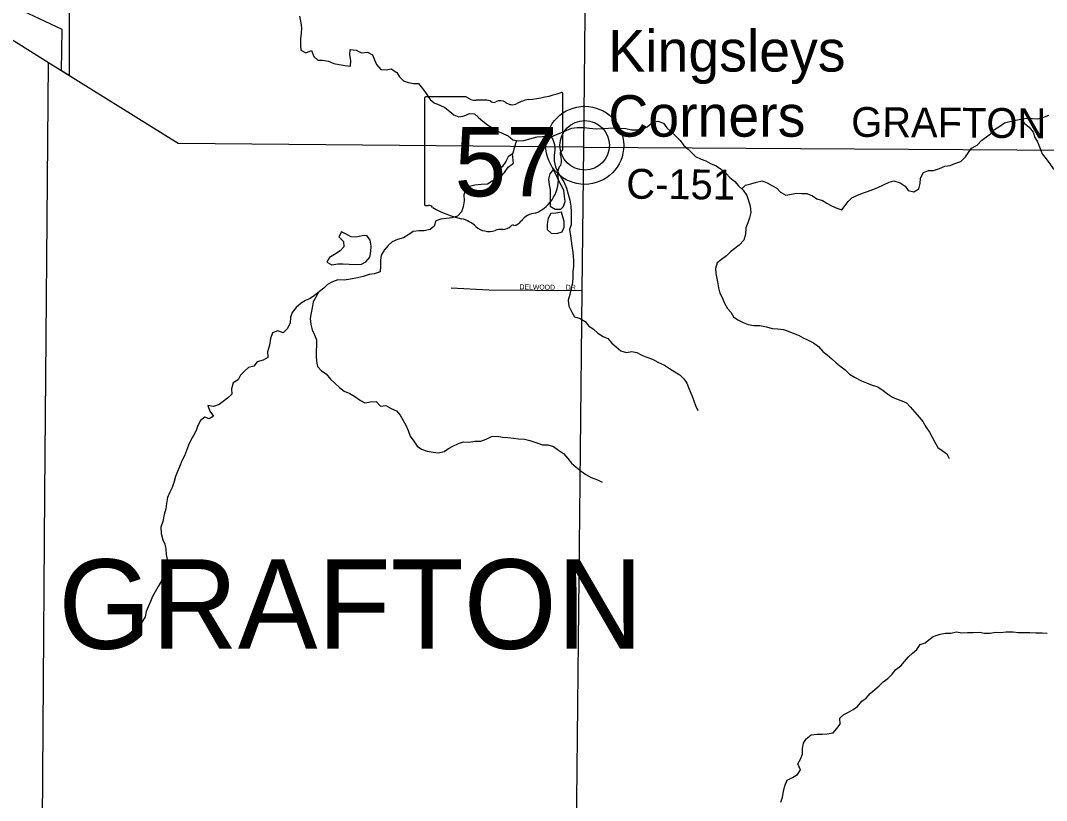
# Model space of a CAD drawing. Extents: x 1857828 to 2277390, y 930619 to 1324581.
# Drawn here: x 2094171 to 2104491, y 1181451 to 1189298 of the extents above; entities that cross this region are included whole.
import ezdxf

# ---------------------------------------------------------------- set-up
doc = ezdxf.new("R2010")
doc.units = 0
for name, color, linetype in [('GM_X_Corporation', 7, 'Continuous'), ('GM_X_County_Road', 7, 'Continuous'), ('GM_X_County_Road_Text', 7, 'Continuous'), ('GM_X_Minor_Lake', 7, 'Continuous'), ('GM_X_Minor_River', 7, 'Continuous'), ('GM_X_State_Location', 7, 'Continuous'), ('GM_X_State_Route', 7, 'Continuous'), ('GM_X_State_Shield', 7, 'Continuous'), ('GM_X_Township_Subdivision', 7, 'Continuous'), ('GM_X_Township_Subdivision_Text', 7, 'Continuous'), ('GM_X_Township_Text', 7, 'Continuous'), ('GM_X_Unincorporated', 7, 'Continuous'), ('GM_X_Unincorporated_Location', 7, 'Continuous'), ('GM_X_Unincorporated_Text', 7, 'Continuous')]:
    doc.layers.add(name, color=color, linetype=linetype)

msp = doc.modelspace()

# ---------------------------------------------------------------- linework, layer by layer
at = {"layer": 'GM_X_Corporation'}
msp.add_lwpolyline([(2093514, 1192144), (2096865, 1192069), (2096840, 1190794), (2094661, 1190795), (2094659, 1188744), (2094584, 1188791), (2094589, 1189208), (2094190, 1189394), (2094190, 1189397), (2093552, 1189568)], dxfattribs=at)
at = {"layer": 'GM_X_County_Road'}
for points in [[(2094381, 1179825), (2094381, 1179825), (2094416, 1184532), (2094454, 1188872)], [(2099838, 1188022), (2105283, 1187989)]]:
    msp.add_lwpolyline(points, dxfattribs=at)
at = {"layer": 'GM_X_Minor_Lake'}
for points in [[(2099119, 1187955), (2099077, 1187927), (2099051, 1187878), (2099017, 1187826), (2098967, 1187784), (2098953, 1187733), (2099006, 1187732)], [(2099006, 1187732), (2099039, 1187770), (2099077, 1187824), (2099129, 1187863), (2099119, 1187955)], [(2099529, 1187799), (2099495, 1187756), (2099483, 1187702), (2099487, 1187646), (2099497, 1187594), (2099500, 1187539), (2099500, 1187485), (2099498, 1187429), (2099548, 1187401), (2099605, 1187399), (2099631, 1187428)], [(2099529, 1187799), (2099495, 1187756), (2099483, 1187702), (2099487, 1187646), (2099497, 1187594), (2099500, 1187539), (2099500, 1187485), (2099498, 1187429), (2099548, 1187401), (2099605, 1187399), (2099631, 1187428)], [(2099631, 1187428), (2099650, 1187476), (2099642, 1187530), (2099636, 1187590), (2099609, 1187642), (2099583, 1187690), (2099561, 1187738), (2099529, 1187799)], [(2099629, 1187424), (2099650, 1187476), (2099642, 1187530), (2099636, 1187590), (2099609, 1187642), (2099583, 1187690), (2099561, 1187738), (2099529, 1187799)], [(2099613, 1187369), (2099557, 1187361), (2099505, 1187357), (2099477, 1187308), (2099469, 1187250), (2099469, 1187196), (2099510, 1187158)], [(2099510, 1187158), (2099564, 1187156), (2099618, 1187172), (2099638, 1187219), (2099639, 1187275), (2099613, 1187369)], [(2097655, 1187134), (2097607, 1187132), (2097547, 1187119), (2097497, 1187123), (2097447, 1187149), (2097400, 1187171), (2097373, 1187120), (2097419, 1187076), (2097423, 1187022), (2097385, 1186982), (2097329, 1186943), (2097279, 1186915), (2097252, 1186867), (2097302, 1186841), (2097364, 1186849), (2097418, 1186851)], [(2097418, 1186851), (2097478, 1186846), (2097542, 1186842), (2097600, 1186848), (2097646, 1186871), (2097686, 1186917), (2097696, 1186973), (2097698, 1187026), (2097688, 1187088), (2097655, 1187134)]]:
    msp.add_lwpolyline(points, dxfattribs=at)
at = {"layer": 'GM_X_Minor_River'}
for points in [[(2096977, 1189340), (2096989, 1189274), (2096996, 1189223), (2096994, 1189171), (2096988, 1189113), (2096986, 1189051), (2096991, 1189000), (2097041, 1188972), (2097097, 1188995), (2097121, 1188937), (2097160, 1188899), (2097210, 1188899), (2097268, 1188889), (2097322, 1188866), (2097376, 1188856), (2097436, 1188844), (2097491, 1188840), (2097494, 1188897), (2097484, 1188951), (2097488, 1189005), (2097548, 1188999), (2097600, 1188971), (2097660, 1188978), (2097713, 1188954), (2097733, 1188902), (2097753, 1188854), (2097796, 1188804), (2097848, 1188802), (2097898, 1188810), (2097956, 1188774), (2097984, 1188732), (2098023, 1188692), (2098075, 1188673), (2098125, 1188665), (2098175, 1188665), (2098213, 1188615), (2098250, 1188563), (2098292, 1188503), (2098332, 1188469), (2098389, 1188447), (2098439, 1188421), (2098489, 1188382), (2098531, 1188350), (2098580, 1188330), (2098632, 1188340), (2098686, 1188363), (2098736, 1188359), (2098778, 1188323), (2098822, 1188285), (2098869, 1188247), (2098923, 1188215), (2098967, 1188189), (2099028, 1188159), (2099076, 1188136), (2099122, 1188096), (2099180, 1188088), (2099232, 1188092), (2099294, 1188109), (2099367, 1188129), (2099421, 1188131), (2099487, 1188134)], [(2101426, 1187604), (2101462, 1187642), (2101518, 1187656), (2101574, 1187673), (2101632, 1187685), (2101682, 1187665), (2101735, 1187635), (2101779, 1187610), (2101815, 1187572), (2101869, 1187540), (2101925, 1187550), (2101975, 1187560), (2102030, 1187559), (2102080, 1187557), (2102136, 1187535), (2102182, 1187505), (2102238, 1187488), (2102281, 1187460), (2102329, 1187432), (2102381, 1187410), (2102431, 1187394), (2102467, 1187436), (2102497, 1187477), (2102533, 1187513), (2102583, 1187536), (2102639, 1187560), (2102689, 1187578), (2102745, 1187599), (2102795, 1187617), (2102851, 1187645), (2102907, 1187672), (2102957, 1187686), (2103019, 1187666), (2103068, 1187630), (2103100, 1187588), (2103158, 1187575), (2103206, 1187605), (2103220, 1187657), (2103224, 1187712), (2103254, 1187770), (2103304, 1187790), (2103356, 1187789), (2103414, 1187809), (2103468, 1187831), (2103522, 1187840), (2103570, 1187858), (2103630, 1187881), (2103676, 1187925), (2103708, 1187969), (2103738, 1188012), (2103793, 1188042), (2103839, 1188095), (2103887, 1188127), (2103929, 1188159), (2103969, 1188202), (2104021, 1188236), (2104067, 1188268), (2104123, 1188281), (2104183, 1188295), (2104247, 1188310), (2104297, 1188316), (2104350, 1188312), (2104404, 1188308), (2104454, 1188321), (2104516, 1188345)], [(2099487, 1188134), (2099509, 1188126), (2099563, 1188152), (2099621, 1188175), (2099667, 1188195), (2099715, 1188215), (2099771, 1188220), (2099841, 1188222), (2099893, 1188216), (2099960, 1188207), (2100024, 1188213), (2100086, 1188215), (2100144, 1188218), (2100204, 1188214), (2100258, 1188210), (2100316, 1188198), (2100371, 1188197), (2100423, 1188205), (2100473, 1188227), (2100527, 1188272), (2100581, 1188286), (2100639, 1188266), (2100673, 1188218), (2100713, 1188180), (2100760, 1188138), (2100806, 1188091), (2100842, 1188041), (2100887, 1188003), (2100923, 1187965), (2100959, 1187929), (2101018, 1187903), (2101066, 1187885), (2101112, 1187859), (2101168, 1187837), (2101223, 1187799), (2101269, 1187758), (2101307, 1187720), (2101355, 1187678), (2101392, 1187634), (2101440, 1187592), (2101478, 1187538), (2101493, 1187488), (2101509, 1187431), (2101517, 1187365), (2101502, 1187313), (2101488, 1187263), (2101466, 1187212), (2101464, 1187150), (2101448, 1187088), (2101401, 1187039), (2101357, 1187005), (2101313, 1186970), (2101271, 1186930), (2101223, 1186892), (2101179, 1186859), (2101161, 1186803), (2101165, 1186751), (2101182, 1186668), (2101192, 1186610), (2101206, 1186556), (2101229, 1186510), (2101253, 1186454), (2101283, 1186402), (2101316, 1186362), (2101342, 1186318), (2101386, 1186288), (2101440, 1186260), (2101491, 1186240), (2101547, 1186228), (2101607, 1186231), (2101675, 1186215), (2101733, 1186201), (2101790, 1186196), (2101846, 1186188), (2101894, 1186174), (2101948, 1186148), (2101996, 1186132), (2102045, 1186105), (2102095, 1186083), (2102149, 1186055), (2102199, 1186019), (2102242, 1185969), (2102284, 1185933), (2102332, 1185893), (2102375, 1185853), (2102425, 1185815), (2102465, 1185783), (2102509, 1185741), (2102568, 1185708), (2102630, 1185674), (2102682, 1185654), (2102737, 1185630), (2102793, 1185614), (2102847, 1185574), (2102891, 1185543), (2102942, 1185509), (2102988, 1185487), (2103036, 1185471), (2103082, 1185451), (2103121, 1185413), (2103167, 1185359)], [(2104239, 1188308), (2104268, 1188266), (2104316, 1188224), (2104358, 1188176), (2104372, 1188121), (2104399, 1188077), (2104427, 1188011), (2104449, 1187957), (2104488, 1187905), (2104524, 1187855), (2104556, 1187813), (2104595, 1187769)], [(2099510, 1188127), (2099525, 1188100), (2099543, 1188052), (2099544, 1187997), (2099538, 1187941), (2099540, 1187887), (2099552, 1187827), (2099575, 1187775), (2099603, 1187727), (2099641, 1187669), (2099664, 1187610), (2099680, 1187552), (2099696, 1187492), (2099707, 1187430), (2099709, 1187374), (2099709, 1187305), (2099710, 1187243), (2099694, 1187195), (2099704, 1187133), (2099710, 1187082), (2099717, 1187032), (2099727, 1186964), (2099733, 1186886), (2099732, 1186827), (2099728, 1186769), (2099726, 1186713), (2099722, 1186659), (2099711, 1186606), (2099695, 1186542), (2099681, 1186486), (2099687, 1186423), (2099716, 1186365), (2099742, 1186317), (2099800, 1186300), (2099849, 1186270), (2099889, 1186224), (2099931, 1186196), (2099977, 1186152), (2100030, 1186120), (2100078, 1186098), (2100118, 1186052), (2100163, 1186014), (2100209, 1185976), (2100267, 1185957), (2100319, 1185967), (2100371, 1185957), (2100420, 1185931), (2100472, 1185911), (2100528, 1185890), (2100582, 1185862), (2100649, 1185830), (2100699, 1185798), (2100751, 1185764), (2100803, 1185732), (2100844, 1185692), (2100874, 1185650), (2100896, 1185590), (2100923, 1185526), (2100943, 1185472), (2100961, 1185424), (2100984, 1185376)], [(2099159, 1188091), (2099144, 1188036), (2099118, 1187954)], [(2099006, 1187732), (2098916, 1187683), (2098868, 1187652), (2098806, 1187648), (2098741, 1187642), (2098687, 1187629), (2098647, 1187599), (2098630, 1187543), (2098632, 1187482), (2098622, 1187424), (2098606, 1187372), (2098568, 1187329), (2098508, 1187311), (2098456, 1187305), (2098398, 1187298), (2098350, 1187282), (2098332, 1187228), (2098290, 1187195), (2098228, 1187183), (2098178, 1187181), (2098120, 1187176), (2098068, 1187138), (2098022, 1187112), (2097964, 1187095), (2097908, 1187071), (2097870, 1187035), (2097830, 1186988), (2097797, 1186938), (2097791, 1186887), (2097793, 1186827), (2097787, 1186769), (2097729, 1186749), (2097677, 1186742), (2097617, 1186722), (2097561, 1186710), (2097489, 1186695), (2097427, 1186687), (2097363, 1186688), (2097309, 1186668), (2097259, 1186642), (2097223, 1186605), (2097177, 1186571), (2097127, 1186532), (2097083, 1186502), (2097037, 1186480), (2096993, 1186455), (2096945, 1186411), (2096903, 1186361), (2096887, 1186312), (2096884, 1186252), (2096852, 1186196), (2096812, 1186155), (2096758, 1186177)], [(2097171, 1186567), (2097115, 1186466), (2097105, 1186406), (2097096, 1186356), (2097086, 1186299), (2097090, 1186239), (2097104, 1186187), (2097127, 1186135), (2097149, 1186085), (2097149, 1186028), (2097146, 1185976), (2097144, 1185926), (2097148, 1185868), (2097158, 1185818), (2097197, 1185774), (2097247, 1185742), (2097289, 1185690), (2097332, 1185650), (2097378, 1185606), (2097426, 1185570), (2097482, 1185546), (2097533, 1185514), (2097591, 1185476), (2097635, 1185453), (2097691, 1185461), (2097747, 1185465), (2097792, 1185419), (2097844, 1185426), (2097900, 1185396), (2097952, 1185370), (2097991, 1185326), (2098021, 1185274), (2098047, 1185226), (2098070, 1185172), (2098090, 1185115), (2098126, 1185067), (2098161, 1185017), (2098205, 1184984), (2098261, 1184964), (2098321, 1184956), (2098375, 1184950), (2098432, 1184963), (2098476, 1184991), (2098521, 1185017), (2098577, 1185044), (2098628, 1185060), (2098680, 1185056), (2098740, 1185067), (2098800, 1185067), (2098854, 1185087), (2098908, 1185114), (2098966, 1185116), (2099018, 1185106), (2099072, 1185103), (2099131, 1185095), (2099181, 1185091), (2099239, 1185087), (2099293, 1185072), (2099365, 1185050), (2099422, 1185030), (2099474, 1185030), (2099532, 1185013), (2099584, 1184977), (2099634, 1184943), (2099677, 1184891), (2099713, 1184845), (2099761, 1184805), (2099810, 1184765), (2099858, 1184729), (2099912, 1184699), (2099973, 1184676), (2100021, 1184654)], [(2096758, 1186177), (2096704, 1186157), (2096684, 1186098), (2096676, 1186032), (2096655, 1185964)], [(2096654, 1185972), (2096659, 1185907), (2096611, 1185881), (2096553, 1185865), (2096517, 1185822), (2096465, 1185808), (2096427, 1185772), (2096385, 1185729), (2096361, 1185683), (2096311, 1185652), (2096293, 1185592), (2096296, 1185538), (2096254, 1185499), (2096208, 1185465), (2096168, 1185435), (2096112, 1185416), (2096056, 1185424), (2096074, 1185368), (2096112, 1185318), (2096070, 1185290), (2096024, 1185309), (2095982, 1185275), (2095956, 1185223), (2095939, 1185174), (2095911, 1185122), (2095883, 1185076), (2095861, 1185025), (2095839, 1184971), (2095820, 1184917), (2095792, 1184868), (2095770, 1184808), (2095750, 1184760), (2095730, 1184709), (2095717, 1184659), (2095695, 1184601), (2095673, 1184554), (2095649, 1184498), (2095641, 1184438), (2095632, 1184385), (2095616, 1184329)], [(2103167, 1185359), (2103211, 1185307), (2103246, 1185265), (2103278, 1185209), (2103314, 1185157), (2103341, 1185107), (2103367, 1185057), (2103399, 1185003), (2103443, 1184971), (2103490, 1184937), (2103512, 1184891)], [(2095616, 1184329), (2095603, 1184258), (2095583, 1184200), (2095587, 1184136), (2095601, 1184075), (2095621, 1184029), (2095631, 1183979), (2095637, 1183926), (2095646, 1183876), (2095646, 1183820), (2095628, 1183758), (2095604, 1183709), (2095587, 1183653), (2095557, 1183603), (2095527, 1183549), (2095498, 1183503), (2095480, 1183453), (2095456, 1183399), (2095436, 1183353), (2095425, 1183300), (2095389, 1183240), (2095373, 1183184)], [(2101820, 1181435), (2101836, 1181485), (2101846, 1181541), (2101860, 1181600), (2101883, 1181654), (2101935, 1181684), (2101985, 1181714), (2102018, 1181758), (2101990, 1181820), (2102020, 1181872), (2102036, 1181922), (2102038, 1181975), (2102047, 1182027), (2102073, 1182073), (2102125, 1182111), (2102182, 1182117), (2102236, 1182120), (2102286, 1182122), (2102345, 1182132), (2102381, 1182176), (2102416, 1182218), (2102412, 1182278), (2102452, 1182316), (2102500, 1182340), (2102547, 1182368), (2102591, 1182398), (2102632, 1182452), (2102676, 1182482), (2102718, 1182528), (2102765, 1182568), (2102809, 1182606), (2102849, 1182644), (2102896, 1182680), (2102940, 1182722), (2102977, 1182770), (2103025, 1182806), (2103061, 1182850), (2103102, 1182896), (2103142, 1182932), (2103186, 1182970), (2103221, 1183022), (2103269, 1183036), (2103309, 1183068), (2103352, 1183102), (2103422, 1183124), (2103475, 1183136), (2103529, 1183135), (2103585, 1183147), (2103640, 1183137), (2103698, 1183141), (2103752, 1183142), (2103817, 1183144), (2103869, 1183136), (2103925, 1183134), (2103978, 1183143), (2104028, 1183141), (2104086, 1183147), (2104157, 1183147), (2104207, 1183140), (2104265, 1183142), (2104324, 1183142), (2104384, 1183139), (2104446, 1183137), (2104497, 1183135)]]:
    msp.add_lwpolyline(points, dxfattribs=at)
at = {"layer": 'GM_X_State_Route'}
for points in [[(2099838, 1188022), (2099873, 1191691), (2099983, 1193016), (2100046, 1193351), (2100069, 1193469)], [(2099838, 1188022), (2095757, 1188061), (2094454, 1188872), (2094036, 1189132), (2093904, 1189205), (2093738, 1189259), (2093178, 1189359), (2092985, 1189398), (2092880, 1189416), (2092821, 1189438), (2092754, 1189482), (2092686, 1189543), (2092624, 1189629), (2092552, 1189730), (2092444, 1189885), (2092426, 1189922), (2092403, 1189999), (2092383, 1190087)], [(2099752, 1180168), (2099752, 1180168), (2099822, 1186577), (2099838, 1188022)]]:
    msp.add_lwpolyline(points, dxfattribs=at)
at = {"layer": 'GM_X_State_Shield'}
for p, q in [((2099625, 1188003), (2099625, 1188556)), ((2098233, 1188511), (2098233, 1187455)), ((2098655, 1188529), (2098247, 1188529)), ((2099625, 1188003), (2099625, 1188003))]:
    msp.add_line(p, q, dxfattribs=at)
for centre, radius, start, end in [((2099130, 1189970), 1476, 275.8445, 288.9065), ((2099610, 1188558), 15.5, 351.8621, 97.738), ((2098249, 1188513), 16.1, 98.1301, 188.1301), ((2098752, 1188652), 156, 231.6195, 271.1119), ((2098804, 1187936), 562, 80.4867, 94.9883), ((2098931, 1188519), 45.1, 219.7921, 297.1024), ((2098997, 1188397), 93.8, 54.4667, 119.1411), ((2099118, 1188564), 113, 233.8562, 294.8282), ((2099318, 1188207), 297, 97.3462, 120.7689), ((2099622, 1187962), 24, 107.944, 210.337), ((2099469, 1187892), 144, 340.033, 23.6496), ((2099609, 1188001), 16.6, 289.6038, 7.7341), ((2099681, 1187772), 105, 136.8065, 186.9296), ((2099212, 1187701), 369, 292.3089, 8.9858), ((2098249, 1187452), 16.3, 171.9584, 258.3066), ((2098252, 1187560), 124, 267.339, 280.6039), ((2098277, 1187394), 44.8, 29.7484, 93.2717), ((2098843, 1188343), 1066, 240.4129, 257.1985), ((2098525, 1186980), 334, 47.1842, 75.836), ((2099368, 1187158), 202, 94.4031, 142.5768), ((2098885, 1187388), 212, 230.7004, 286.2918), ((2099008, 1187023), 174, 85.6951, 111.2099), ((2099023, 1187309), 113, 268.777, 315.5493), ((2099125, 1187207), 31.8, 65.7517, 132.6484), ((2099112, 1187352), 119, 282.8732, 323.2771)]:
    msp.add_arc(centre, radius, start, end, dxfattribs=at)
at = {"layer": 'GM_X_Township_Subdivision'}
msp.add_lwpolyline([(2099822, 1186577), (2098883, 1186586), (2098502, 1186606)], dxfattribs=at)
at = {"layer": 'GM_X_Unincorporated'}
for radius in [393, 249]:
    msp.add_circle((2099846, 1188042), radius, dxfattribs=at)
at = {"layer": 'GM_X_Unincorporated_Location'}
msp.add_line((2099846, 1188042), (2099846, 1188042), dxfattribs=at)

# ---------------------------------------------------------------- texts
at = {"layer": 'GM_X_County_Road_Text'}
for s, rotation, p in [('GRAFTON', 359.5634, (2102526, 1188128)), ('C-151', 359.4494, (2100263, 1187506))]:
    msp.add_text(s, height=300, rotation=rotation, dxfattribs=at).set_placement(p)
at = {"layer": 'GM_X_State_Location'}
msp.add_text('57', height=1, rotation=0, dxfattribs=at).set_placement((2098662, 1187840))
for s in ['s', 'r']:
    msp.add_text(s, height=1, dxfattribs=at).set_placement((2098914, 1187913))
at = {"layer": 'GM_X_State_Shield'}
msp.add_text('57', height=696.1, dxfattribs=at).set_placement((2098538, 1187529))
at = {"layer": 'GM_X_Township_Subdivision_Text'}
for s, rotation, p in [('DELWOOD', 359.182, (2099190, 1186594)), ('DR', 0, (2099656, 1186589))]:
    msp.add_text(s, height=50, rotation=rotation, dxfattribs=at).set_placement(p)
at = {"layer": 'GM_X_Township_Text'}
msp.add_text('GRAFTON', height=900, rotation=0, dxfattribs=at).set_placement((2094551, 1182977))
at = {"layer": 'GM_X_Unincorporated_Text'}
for s, p in [('Kingsleys', (2100083, 1188784)), ('Corners', (2100083, 1188129))]:
    msp.add_text(s, height=417, rotation=0, dxfattribs=at).set_placement(p)

doc.saveas('drawing.dxf')
